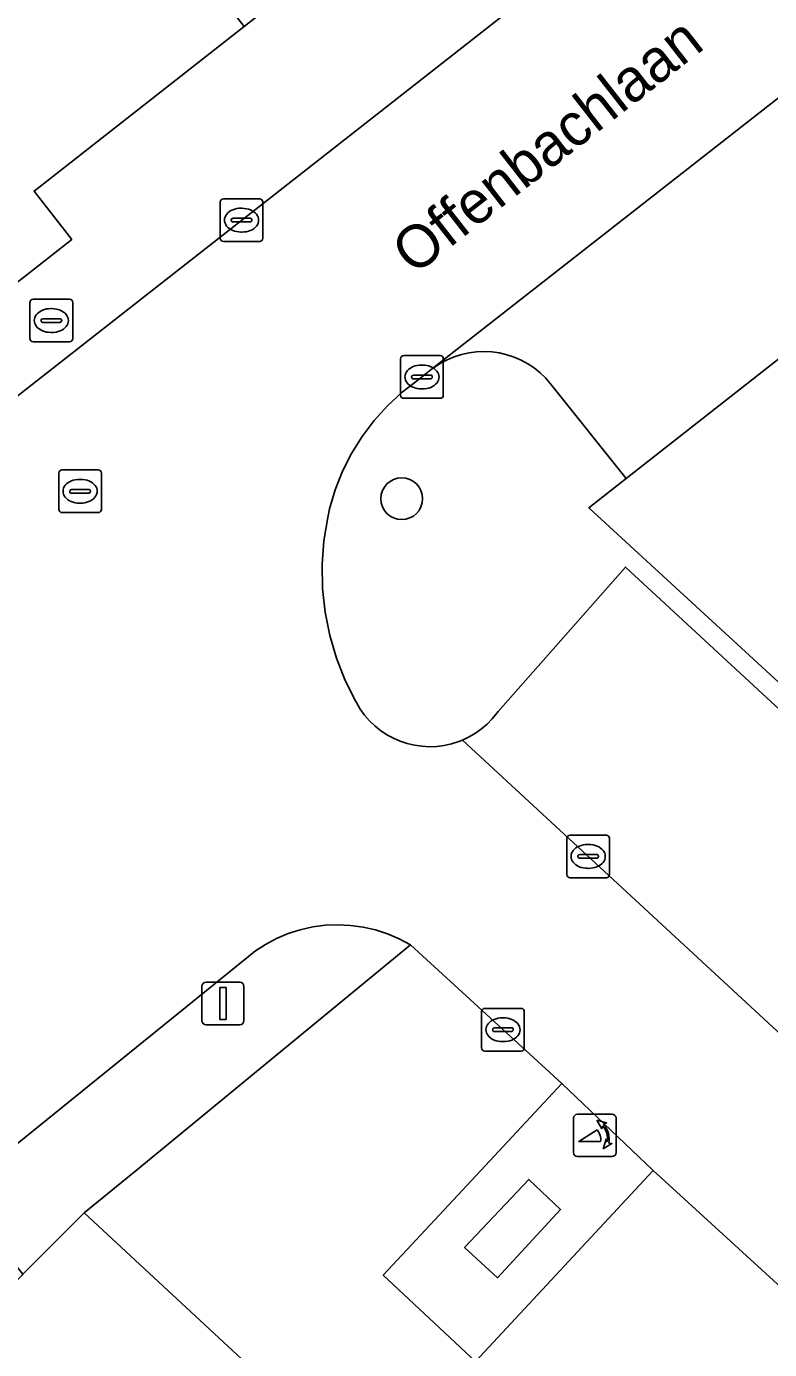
# Model space of a CAD drawing. Extents: x 159217 to 160349, y 381246 to 382172.
# Drawn here: x 159793.07 to 159810.5, y 381745.8 to 381776.83 of the extents above; entities that cross this region are included whole.
import ezdxf

# ---------------------------------------------------------------- set-up
doc = ezdxf.new("R2010")
doc.units = 0
for name, color, linetype in [('IMGEO_Boom', 7, 'Continuous'), ('IMGEO_Brandkraan', 7, 'Continuous'), ('IMGEO_Groenvoorziening', 7, 'Continuous'), ('IMGEO_Kolk', 7, 'Continuous'), ('IMGEO_Lichtmast', 7, 'Continuous'), ('IMGEO_Openbare_ruimte_label', 7, 'Continuous'), ('IMGEO_Pand', 7, 'Continuous'), ('IMGEO_Parkeervlak_open', 7, 'Continuous'), ('IMGEO_Poller', 7, 'Continuous'), ('IMGEO_Rijbaan_lokaal_open', 7, 'Continuous'), ('IMGEO_Rioolput', 7, 'Continuous'), ('IMGEO_Voetpad_open', 7, 'Continuous')]:
    doc.layers.add(name, color=color, linetype=linetype)

msp = doc.modelspace()

# ---------------------------------------------------------------- linework, layer by layer
at = {"layer": 'IMGEO_Boom'}
msp.add_circle((159801.87, 381765.753), 0.489, dxfattribs=at)
at = {"layer": 'IMGEO_Brandkraan'}
for p, q in [((159793.152, 381769.507), (159793.152, 381770.359)), ((159793.227, 381770.433), (159794.079, 381770.433)), ((159793.64, 381770.213), (159793.665, 381770.213)), ((159794.153, 381770.359), (159794.153, 381769.507)), ((159793.411, 381769.927), (159793.411, 381769.939)), ((159793.849, 381769.89), (159793.451, 381769.89)), ((159793.454, 381769.976), (159793.852, 381769.976)), ((159793.895, 381769.939), (159793.895, 381769.927)), ((159793.663, 381769.653), (159793.638, 381769.653)), ((159794.079, 381769.433), (159793.227, 381769.433))]:
    msp.add_line(p, q, dxfattribs=at)
for points in [[(159793.152, 381769.507), (159793.152, 381770.359)], [(159793.227, 381770.433), (159794.079, 381770.433)], [(159794.153, 381770.359), (159794.153, 381769.507)], [(159794.079, 381769.433), (159793.227, 381769.433)]]:
    msp.add_lwpolyline(points, dxfattribs=at)
for centre, radius, start, end in [((159793.229, 381770.357), 0.0765, 91.552, 178.448), ((159793.229, 381770.357), 0.0765, 91.552, 178.448), ((159794.077, 381770.357), 0.0765, 1.552, 88.448), ((159794.077, 381770.357), 0.0765, 1.552, 88.448), ((159793.451, 381769.936), 0.0403, 85.8775, 175.7526), ((159793.448, 381769.926), 0.0366, 178.938, 274.7102), ((159793.852, 381769.933), 0.043, 264.8664, 352.4533), ((159793.856, 381769.938), 0.0386, 1.7309, 96.639), ((159793.229, 381769.509), 0.0765, 181.552, 268.448), ((159793.229, 381769.509), 0.0765, 181.552, 268.448), ((159794.077, 381769.509), 0.0765, 271.552, 358.448), ((159794.077, 381769.509), 0.0765, 271.552, 358.448)]:
    msp.add_arc(centre, radius, start, end, dxfattribs=at)
for centre, major_axis, ratio, start_param, end_param in [((159793.639, 381769.933), (-0.387, 0.002), 0.722429, 4.712389, 7.853982), ((159793.664, 381769.933), (-0.39, 0.002), 0.717154, 1.570796, 4.712389)]:
    msp.add_ellipse(centre, major_axis=major_axis, ratio=ratio, start_param=start_param, end_param=end_param, dxfattribs=at)
at = {"layer": 'IMGEO_Groenvoorziening'}
msp.add_lwpolyline([(159813.982, 381771.599), (159807.132, 381766.225), (159806.261, 381765.542), (159823.171, 381750)], dxfattribs=at)
for points in [[(159802.073, 381755.288), (159795.639, 381750), (159794.426, 381749.008), (159805.302, 381738.901), (159816.282, 381728.697), (159827.45, 381718.318), (159834.247, 381725.568), (159829.716, 381729.773), (159825.509, 381725.247), (159823.334, 381727.267), (159827.53, 381731.802), (159819.769, 381739.005), (159815.597, 381734.475), (159813.411, 381736.488), (159817.605, 381741.003), (159807.766, 381750), (159803.599, 381745.515), (159801.436, 381747.543), (159802.207, 381748.37), (159803.726, 381750), (159805.628, 381752.041)], [(159805.595, 381749.085), (159804.851, 381749.79), (159803.345, 381748.194), (159804.117, 381747.482)]]:
    msp.add_lwpolyline(points, close=True, dxfattribs=at)
at = {"layer": 'IMGEO_Kolk'}
for p, q in [((159797.613, 381771.861), (159797.613, 381772.713)), ((159797.688, 381772.787), (159798.54, 381772.787)), ((159798.614, 381772.713), (159798.614, 381771.861)), ((159798.101, 381772.567), (159798.126, 381772.567)), ((159797.872, 381772.281), (159797.872, 381772.293)), ((159798.31, 381772.244), (159797.912, 381772.244)), ((159797.915, 381772.33), (159798.313, 381772.33)), ((159798.356, 381772.293), (159798.356, 381772.281)), ((159798.54, 381771.787), (159797.688, 381771.787)), ((159798.124, 381772.007), (159798.099, 381772.007)), ((159801.844, 381768.183), (159801.844, 381769.035)), ((159801.919, 381769.109), (159802.771, 381769.109)), ((159802.845, 381769.035), (159802.845, 381768.183)), ((159802.146, 381768.652), (159802.544, 381768.652)), ((159802.332, 381768.889), (159802.357, 381768.889)), ((159802.103, 381768.603), (159802.103, 381768.615)), ((159802.541, 381768.566), (159802.143, 381768.566)), ((159802.355, 381768.329), (159802.33, 381768.329)), ((159802.587, 381768.615), (159802.587, 381768.603)), ((159802.771, 381768.109), (159801.919, 381768.109)), ((159805.742, 381756.938), (159805.742, 381757.79)), ((159805.817, 381757.864), (159806.669, 381757.864)), ((159806.743, 381757.79), (159806.743, 381756.938)), ((159806.23, 381757.644), (159806.255, 381757.644)), ((159806.001, 381757.358), (159806.001, 381757.37)), ((159806.439, 381757.321), (159806.041, 381757.321)), ((159806.044, 381757.407), (159806.442, 381757.407)), ((159806.485, 381757.37), (159806.485, 381757.358)), ((159806.669, 381756.864), (159805.817, 381756.864)), ((159806.253, 381757.084), (159806.228, 381757.084)), ((159803.819, 381753.799), (159804.671, 381753.799)), ((159803.744, 381752.873), (159803.744, 381753.725)), ((159804.232, 381753.579), (159804.257, 381753.579)), ((159804.745, 381753.725), (159804.745, 381752.873)), ((159804.003, 381753.293), (159804.003, 381753.305)), ((159804.441, 381753.256), (159804.043, 381753.256)), ((159804.046, 381753.342), (159804.444, 381753.342)), ((159804.487, 381753.305), (159804.487, 381753.293)), ((159804.255, 381753.019), (159804.23, 381753.019)), ((159804.671, 381752.799), (159803.819, 381752.799))]:
    msp.add_line(p, q, dxfattribs=at)
for points in [[(159797.613, 381771.861), (159797.613, 381772.713)], [(159797.688, 381772.787), (159798.54, 381772.787)], [(159798.614, 381772.713), (159798.614, 381771.861)], [(159798.54, 381771.787), (159797.688, 381771.787)], [(159801.844, 381768.183), (159801.844, 381769.035)], [(159801.919, 381769.109), (159802.771, 381769.109)], [(159802.845, 381769.035), (159802.845, 381768.183)], [(159802.771, 381768.109), (159801.919, 381768.109)], [(159805.742, 381756.938), (159805.742, 381757.79)], [(159805.817, 381757.864), (159806.669, 381757.864)], [(159806.743, 381757.79), (159806.743, 381756.938)], [(159806.669, 381756.864), (159805.817, 381756.864)], [(159803.819, 381753.799), (159804.671, 381753.799)], [(159803.744, 381752.873), (159803.744, 381753.725)], [(159804.745, 381753.725), (159804.745, 381752.873)], [(159804.671, 381752.799), (159803.819, 381752.799)]]:
    msp.add_lwpolyline(points, dxfattribs=at)
for centre, radius, start, end in [((159797.69, 381772.711), 0.0765, 91.552, 178.448), ((159797.69, 381772.711), 0.0765, 91.552, 178.448), ((159798.538, 381772.711), 0.0765, 1.552, 88.448), ((159798.538, 381772.711), 0.0765, 1.552, 88.448), ((159797.912, 381772.29), 0.0403, 85.8775, 175.7526), ((159797.909, 381772.28), 0.0366, 178.938, 274.7102), ((159798.313, 381772.287), 0.043, 264.8664, 352.4533), ((159798.317, 381772.292), 0.0386, 1.7309, 96.639), ((159797.69, 381771.863), 0.0765, 181.552, 268.448), ((159797.69, 381771.863), 0.0765, 181.552, 268.448), ((159798.538, 381771.863), 0.0765, 271.552, 358.448), ((159798.538, 381771.863), 0.0765, 271.552, 358.448), ((159801.921, 381769.033), 0.0765, 91.552, 178.448), ((159801.921, 381769.033), 0.0765, 91.552, 178.448), ((159802.769, 381769.033), 0.0765, 1.552, 88.448), ((159802.769, 381769.033), 0.0765, 1.552, 88.448), ((159802.143, 381768.612), 0.0403, 85.8775, 175.7526), ((159802.548, 381768.614), 0.0386, 1.7309, 96.639), ((159802.14, 381768.602), 0.0366, 178.938, 274.7102), ((159802.544, 381768.609), 0.043, 264.8664, 352.4533), ((159801.921, 381768.185), 0.0765, 181.552, 268.448), ((159801.921, 381768.185), 0.0765, 181.552, 268.448), ((159802.769, 381768.185), 0.0765, 271.552, 358.448), ((159802.769, 381768.185), 0.0765, 271.552, 358.448), ((159805.819, 381757.788), 0.0765, 91.552, 178.448), ((159805.819, 381757.788), 0.0765, 91.552, 178.448), ((159806.667, 381757.788), 0.0765, 1.552, 88.448), ((159806.667, 381757.788), 0.0765, 1.552, 88.448), ((159806.041, 381757.367), 0.0403, 85.8775, 175.7526), ((159806.038, 381757.357), 0.0366, 178.938, 274.7102), ((159806.442, 381757.364), 0.043, 264.8664, 352.4533), ((159806.446, 381757.369), 0.0386, 1.7309, 96.639), ((159805.819, 381756.94), 0.0765, 181.552, 268.448), ((159805.819, 381756.94), 0.0765, 181.552, 268.448), ((159806.667, 381756.94), 0.0765, 271.552, 358.448), ((159806.667, 381756.94), 0.0765, 271.552, 358.448), ((159803.821, 381753.723), 0.0765, 91.552, 178.448), ((159803.821, 381753.723), 0.0765, 91.552, 178.448), ((159804.669, 381753.723), 0.0765, 1.552, 88.448), ((159804.669, 381753.723), 0.0765, 1.552, 88.448), ((159804.043, 381753.302), 0.0403, 85.8775, 175.7526), ((159804.04, 381753.292), 0.0366, 178.938, 274.7102), ((159804.444, 381753.299), 0.043, 264.8664, 352.4533), ((159804.448, 381753.304), 0.0386, 1.7309, 96.639), ((159803.821, 381752.875), 0.0765, 181.552, 268.448), ((159803.821, 381752.875), 0.0765, 181.552, 268.448), ((159804.669, 381752.875), 0.0765, 271.552, 358.448), ((159804.669, 381752.875), 0.0765, 271.552, 358.448)]:
    msp.add_arc(centre, radius, start, end, dxfattribs=at)
for centre, major_axis, ratio, start_param, end_param in [((159798.1, 381772.287), (-0.387, 0.002), 0.722429, 4.712389, 7.853982), ((159798.125, 381772.287), (-0.39, 0.002), 0.717154, 1.570796, 4.712389), ((159802.331, 381768.609), (-0.387, 0.002), 0.722429, 4.712389, 7.853982), ((159802.356, 381768.609), (-0.39, 0.002), 0.717154, 1.570796, 4.712389), ((159806.229, 381757.364), (-0.387, 0.002), 0.722429, 4.712389, 7.853982), ((159806.254, 381757.364), (-0.39, 0.002), 0.717154, 1.570796, 4.712389), ((159804.231, 381753.299), (-0.387, 0.002), 0.722429, 4.712389, 7.853982), ((159804.256, 381753.299), (-0.39, 0.002), 0.717154, 1.570796, 4.712389)]:
    msp.add_ellipse(centre, major_axis=major_axis, ratio=ratio, start_param=start_param, end_param=end_param, dxfattribs=at)
at = {"layer": 'IMGEO_Lichtmast'}
for p, q in [((159797.281, 381754.414), (159798.071, 381754.414)), ((159798.071, 381754.414), (159797.281, 381754.414)), ((159797.181, 381753.514), (159797.181, 381754.314)), ((159797.181, 381754.314), (159797.181, 381753.514)), ((159798.171, 381754.314), (159798.171, 381753.514)), ((159798.171, 381753.514), (159798.171, 381754.314)), ((159798.071, 381753.414), (159797.281, 381753.414)), ((159797.281, 381753.414), (159798.071, 381753.414))]:
    msp.add_line(p, q, dxfattribs=at)
msp.add_lwpolyline([(159797.601, 381754.289), (159797.751, 381754.289), (159797.751, 381753.539), (159797.601, 381753.539), (159797.601, 381754.289)], dxfattribs=at)
for centre, start, end in [((159797.281, 381754.314), 90, 180), ((159797.281, 381754.314), 90, 180), ((159798.071, 381754.314), 0, 90), ((159798.071, 381754.314), 360, 90), ((159797.281, 381753.514), 180, 270), ((159797.281, 381753.514), 180, 270), ((159798.071, 381753.514), 270, 0), ((159798.071, 381753.514), 270, 0)]:
    msp.add_arc(centre, 0.1, start, end, dxfattribs=at)
at = {"layer": 'IMGEO_Pand'}
for points in [[(159791.568, 381785.266), (159784.528, 381779.748), (159779.62, 381775.901), (159786.23, 381767.468), (159791.311, 381771.451), (159792.197, 381770.319), (159794.133, 381771.836), (159793.247, 381772.968), (159798.178, 381776.833)], [(159805.302, 381738.901), (159794.426, 381749.008), (159792.986, 381747.564), (159792.965, 381747.543), (159786.788, 381741.347), (159791.553, 381736.947), (159790.638, 381735.955), (159792.459, 381734.272), (159793.375, 381735.264), (159797.974, 381731.016)]]:
    msp.add_lwpolyline(points, close=True, dxfattribs=at)
at = {"layer": 'IMGEO_Parkeervlak_open'}
msp.add_lwpolyline([(159825.78, 381786.951), (159802.563, 381768.781), (159802.63, 381768.831), (159802.78, 381768.929), (159802.938, 381769.012), (159803.103, 381769.082), (159803.273, 381769.136), (159803.448, 381769.175), (159803.625, 381769.198), (159803.804, 381769.206), (159803.982, 381769.197), (159804.16, 381769.172), (159804.334, 381769.132), (159804.504, 381769.076), (159804.668, 381769.005), (159804.826, 381768.92), (159804.975, 381768.821), (159805.114, 381768.71), (159805.243, 381768.586), (159805.361, 381768.451), (159807.132, 381766.225), (159813.982, 381771.599)], dxfattribs=at)
msp.add_lwpolyline([(159833.311, 381732.333), (159833.59, 381732.834), (159837.026, 381736.496), (159822.422, 381750), (159807.121, 381764.149), (159804.13, 381760.763), (159804.103, 381760.725), (159803.993, 381760.591), (159803.872, 381760.466), (159803.741, 381760.353), (159803.599, 381760.253), (159803.45, 381760.165), (159803.293, 381760.091), (159814.206, 381750)], close=True, dxfattribs=at)
at = {"layer": 'IMGEO_Poller'}
for p, q in [((159806.802, 381751.319), (159805.994, 381751.319)), ((159806.802, 381751.319), (159805.994, 381751.319)), ((159805.9, 381751.224), (159805.9, 381750.417)), ((159805.9, 381751.224), (159805.9, 381750.417)), ((159806.896, 381750.417), (159806.896, 381751.224)), ((159806.896, 381750.417), (159806.896, 381751.224)), ((159805.994, 381750.322), (159806.802, 381750.322)), ((159805.994, 381750.322), (159806.802, 381750.322))]:
    msp.add_line(p, q, dxfattribs=at)
for points in [[(159806.535, 381750.675), (159806.022, 381750.675), (159806.452, 381750.95)], [(159806.579, 381751.048), (159806.567, 381750.975), (159806.442, 381751.18)], [(159806.442, 381751.18), (159806.673, 381751.114), (159806.602, 381751.082)], [(159806.595, 381750.503), (159806.661, 381750.734), (159806.691, 381750.666)], [(159806.727, 381750.639), (159806.799, 381750.628), (159806.595, 381750.503)]]:
    msp.add_lwpolyline(points, dxfattribs=at)
for centre, radius, start, end in [((159805.994, 381751.224), 0.0946, 90, 180), ((159805.994, 381751.224), 0.0946, 90, 180), ((159806.802, 381751.224), 0.0946, 0, 90), ((159806.802, 381751.224), 0.0946, 0, 90), ((159806.207, 381750.725), 0.332, 351.3247, 42.4854), ((159806.221, 381750.735), 0.476, 351.7527, 41.1691), ((159806.221, 381750.735), 0.516, 349.3569, 42.2912), ((159805.994, 381750.417), 0.0946, 180, 270), ((159805.994, 381750.417), 0.0946, 180, 270), ((159806.802, 381750.417), 0.0946, 270, 0), ((159806.802, 381750.417), 0.0946, 270, 0)]:
    msp.add_arc(centre, radius, start, end, dxfattribs=at)
at = {"layer": 'IMGEO_Rijbaan_lokaal_open'}
for points in [[(159825.925, 381794.084), (159791.101, 381766.789)], [(159814.206, 381750), (159803.293, 381760.091), (159803.206, 381760.057), (159803.039, 381760.004), (159802.868, 381759.966), (159802.694, 381759.944), (159802.52, 381759.937), (159802.345, 381759.946), (159802.172, 381759.97), (159802.001, 381760.01), (159801.835, 381760.065), (159801.674, 381760.135), (159801.521, 381760.218), (159801.375, 381760.315), (159801.239, 381760.425), (159801.113, 381760.546), (159800.998, 381760.679), (159800.895, 381760.821), (159800.806, 381760.971), (159800.793, 381760.994), (159800.543, 381761.493), (159800.339, 381762.012), (159800.182, 381762.547), (159800.073, 381763.094), (159800.014, 381763.649), (159800.004, 381764.207), (159800.044, 381764.763), (159800.134, 381765.314), (159800.18, 381765.515), (159800.312, 381765.963), (159800.484, 381766.398), (159800.694, 381766.815), (159800.94, 381767.212), (159801.221, 381767.585), (159801.534, 381767.931), (159801.877, 381768.249), (159802.247, 381768.534), (159802.563, 381768.781), (159825.78, 381786.951)], [(159792.072, 381750), (159798.443, 381755.151), (159798.673, 381755.3), (159798.935, 381755.439), (159799.209, 381755.555), (159799.492, 381755.645), (159799.783, 381755.71), (159800.077, 381755.749), (159800.374, 381755.761), (159800.671, 381755.747), (159800.966, 381755.706), (159801.256, 381755.639), (159801.538, 381755.547), (159801.811, 381755.429), (159802.073, 381755.288), (159805.628, 381752.041), (159807.766, 381750), (159817.605, 381741.003)]]:
    msp.add_lwpolyline(points, dxfattribs=at)
at = {"layer": 'IMGEO_Rioolput'}
for p, q in [((159793.827, 381765.502), (159793.827, 381766.354)), ((159793.902, 381766.428), (159794.754, 381766.428)), ((159794.315, 381766.208), (159794.34, 381766.208)), ((159794.828, 381766.354), (159794.828, 381765.502)), ((159794.086, 381765.922), (159794.086, 381765.934)), ((159794.524, 381765.885), (159794.126, 381765.885)), ((159794.129, 381765.971), (159794.527, 381765.971)), ((159794.57, 381765.934), (159794.57, 381765.922)), ((159794.338, 381765.648), (159794.313, 381765.648)), ((159794.754, 381765.428), (159793.902, 381765.428))]:
    msp.add_line(p, q, dxfattribs=at)
for points in [[(159793.827, 381765.502), (159793.827, 381766.354)], [(159793.902, 381766.428), (159794.754, 381766.428)], [(159794.828, 381766.354), (159794.828, 381765.502)], [(159794.754, 381765.428), (159793.902, 381765.428)]]:
    msp.add_lwpolyline(points, dxfattribs=at)
for centre, radius, start, end in [((159793.904, 381766.352), 0.0765, 91.552, 178.448), ((159793.904, 381766.352), 0.0765, 91.552, 178.448), ((159794.752, 381766.352), 0.0765, 1.552, 88.448), ((159794.752, 381766.352), 0.0765, 1.552, 88.448), ((159794.126, 381765.931), 0.0403, 85.8775, 175.7526), ((159794.123, 381765.921), 0.0366, 178.938, 274.7102), ((159794.527, 381765.928), 0.043, 264.8664, 352.4533), ((159794.531, 381765.933), 0.0386, 1.7309, 96.639), ((159793.904, 381765.504), 0.0765, 181.552, 268.448), ((159793.904, 381765.504), 0.0765, 181.552, 268.448), ((159794.752, 381765.504), 0.0765, 271.552, 358.448), ((159794.752, 381765.504), 0.0765, 271.552, 358.448)]:
    msp.add_arc(centre, radius, start, end, dxfattribs=at)
for centre, major_axis, ratio, start_param, end_param in [((159794.314, 381765.928), (-0.387, 0.002), 0.722429, 4.712389, 7.853982), ((159794.339, 381765.928), (-0.39, 0.002), 0.717154, 1.570796, 4.712389)]:
    msp.add_ellipse(centre, major_axis=major_axis, ratio=ratio, start_param=start_param, end_param=end_param, dxfattribs=at)
at = {"layer": 'IMGEO_Voetpad_open'}
for points in [[(159814.891, 381789.932), (159809.975, 381786.08), (159805.06, 381782.228), (159805.949, 381781.093), (159803.997, 381779.564), (159803.109, 381780.698), (159798.178, 381776.833), (159793.247, 381772.968), (159794.133, 381771.836), (159792.197, 381770.319), (159791.311, 381771.451), (159786.23, 381767.468), (159786.6, 381766.817), (159785.627, 381766.031), (159784.152, 381764.768), (159781.398, 381762.428), (159782.092, 381761.449), (159782.256, 381761.24), (159785.776, 381763.081), (159787.913, 381764.35), (159789.927, 381765.805), (159791.101, 381766.789), (159825.925, 381794.084)], [(159823.171, 381750), (159806.261, 381765.542), (159807.132, 381766.225), (159805.361, 381768.451), (159805.243, 381768.586), (159805.114, 381768.71), (159804.975, 381768.821), (159804.826, 381768.92), (159804.668, 381769.005), (159804.504, 381769.076), (159804.334, 381769.132), (159804.16, 381769.172), (159803.982, 381769.197), (159803.804, 381769.206), (159803.625, 381769.198), (159803.448, 381769.175), (159803.273, 381769.136), (159803.103, 381769.082), (159802.938, 381769.012), (159802.78, 381768.929), (159802.63, 381768.831), (159802.563, 381768.781), (159802.247, 381768.534), (159801.877, 381768.249), (159801.534, 381767.931), (159801.221, 381767.585), (159800.94, 381767.212), (159800.694, 381766.815), (159800.484, 381766.398), (159800.312, 381765.963), (159800.18, 381765.515), (159800.134, 381765.314), (159800.044, 381764.763), (159800.004, 381764.207), (159800.014, 381763.649), (159800.073, 381763.094), (159800.182, 381762.547), (159800.339, 381762.012), (159800.543, 381761.493), (159800.793, 381760.994), (159800.806, 381760.971), (159800.895, 381760.821), (159800.998, 381760.679), (159801.113, 381760.546), (159801.239, 381760.425), (159801.375, 381760.315), (159801.521, 381760.218), (159801.674, 381760.135), (159801.835, 381760.065), (159802.001, 381760.01), (159802.172, 381759.97), (159802.345, 381759.946), (159802.52, 381759.937), (159802.694, 381759.944), (159802.868, 381759.966), (159803.039, 381760.004), (159803.206, 381760.057), (159803.293, 381760.091), (159803.45, 381760.165), (159803.599, 381760.253), (159803.741, 381760.353), (159803.872, 381760.466), (159803.993, 381760.591), (159804.103, 381760.725), (159804.13, 381760.763), (159807.121, 381764.149), (159822.422, 381750)]]:
    msp.add_lwpolyline(points, dxfattribs=at)
for points in [[(159802.073, 381755.288), (159801.811, 381755.429), (159801.538, 381755.547), (159801.256, 381755.639), (159800.966, 381755.706), (159800.671, 381755.747), (159800.374, 381755.761), (159800.077, 381755.749), (159799.783, 381755.71), (159799.492, 381755.645), (159799.209, 381755.555), (159798.935, 381755.439), (159798.673, 381755.3), (159798.443, 381755.151), (159792.072, 381750), (159791.444, 381749.492), (159791.537, 381749.373), (159792.986, 381747.564), (159794.426, 381749.008), (159795.639, 381750)], [(159805.628, 381752.041), (159803.726, 381750), (159802.207, 381748.37), (159801.436, 381747.543), (159803.599, 381745.515), (159807.766, 381750)], [(159804.117, 381747.482), (159803.345, 381748.194), (159804.851, 381749.79), (159805.595, 381749.085)]]:
    msp.add_lwpolyline(points, close=True, dxfattribs=at)

# ---------------------------------------------------------------- texts
at = {"layer": 'IMGEO_Openbare_ruimte_label'}
msp.add_text('Offenbachlaan', height=1, rotation=38.0157, dxfattribs=at).set_placement((159802.156, 381770.974))

doc.saveas('drawing.dxf')
